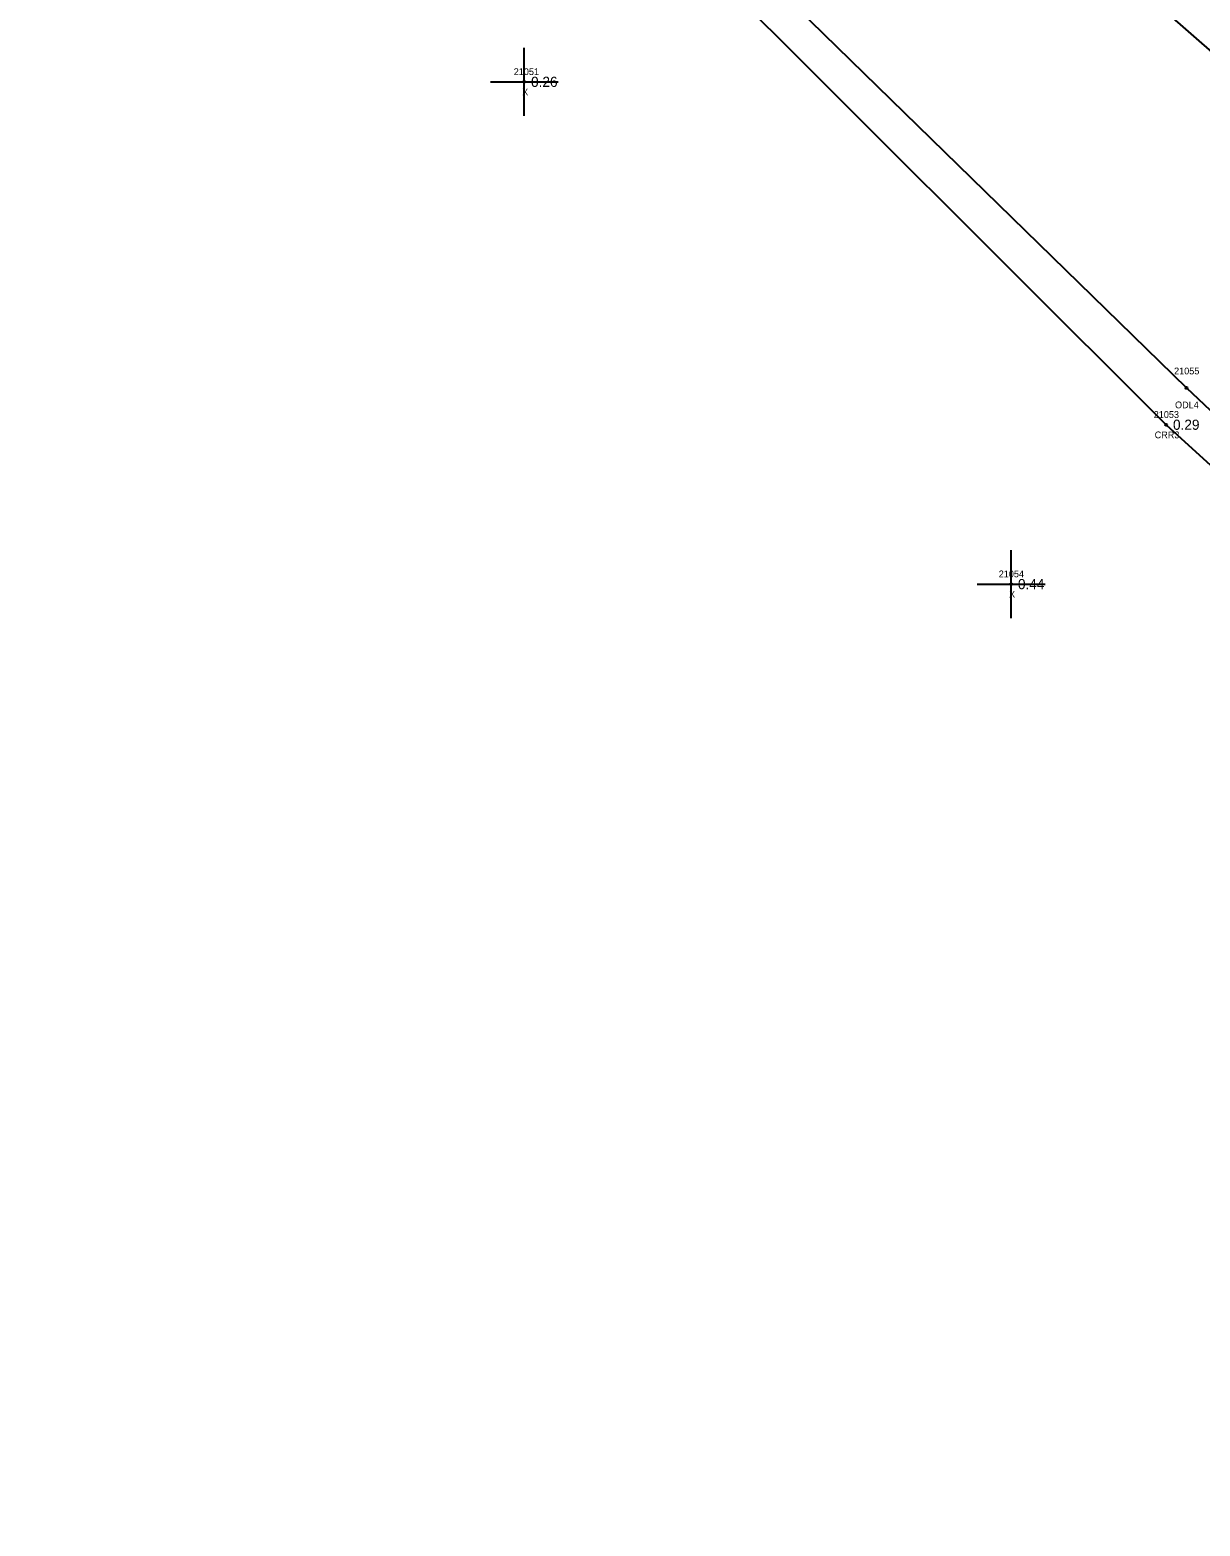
# Model space of a CAD drawing. Extents: x 2608745 to 2610333, y 641917 to 643463.
# Drawn here: x 2609542.9 to 2609715.3, y 642225.6 to 642446.2 of the extents above; entities that cross this region are included whole.
import ezdxf

# ---------------------------------------------------------------- set-up
doc = ezdxf.new("R2010")
doc.units = 0
for name, color, linetype in [('RD_EX_H2O', 7, 'Continuous'), ('RD_EX_H2O_txCode', 7, 'Continuous'), ('RD_EX_Misc', 7, 'Continuous'), ('RD_EX_Misc_txCode', 7, 'Continuous'), ('RD_EX_TX_H2O_ELEV', 7, 'Continuous'), ('RD_EX_TX_Misc_ELEV', 7, 'Continuous'), ('RD_SMD_Locator', 7, 'Continuous')]:
    doc.layers.add(name, color=color, linetype=linetype)

msp = doc.modelspace()

# ---------------------------------------------------------------- linework, layer by layer
at = {"layer": 'RD_EX_H2O'}
for points in [[(2609545.26, 642628.98), (2609557.91, 642602.6), (2609591.74, 642540.6), (2609658.48, 642494.06), (2609739.9, 642422.86), (2609760.07, 642378.85), (2609808.54, 642339.07), (2609896.37, 642269.89), (2609925.48, 642240.69), (2609915.11, 642188.91), (2609891.33, 642158.21), (2609835.84, 642063.03)], [(2609518.22, 642586.65), (2609536.97, 642578.99), (2609575.62, 642520.95), (2609643.94, 642461.12), (2609713.29, 642393.38), (2609797.14, 642314.29), (2609845.08, 642297.38), (2609901.61, 642240.2), (2609849.12, 642177.48), (2609793.89, 642090.6)], [(2609514.45, 642579.97), (2609534.32, 642569.3), (2609569.82, 642513.21), (2609640.11, 642458.03), (2609710.3, 642387.96), (2609794.99, 642310.91), (2609843.78, 642290.31), (2609891.67, 642241.7), (2609844.05, 642181.23), (2609787.66, 642090.39)]]:
    msp.add_lwpolyline(points, dxfattribs=at)
at = {"layer": 'RD_EX_Misc'}
for p, q in [((2609615.7, 642433.5), (2609615.7, 642443.5)), ((2609610.7, 642438.5), (2609620.7, 642438.5)), ((2609687.45, 642359.47), (2609687.45, 642369.47)), ((2609682.45, 642364.47), (2609692.45, 642364.47))]:
    msp.add_line(p, q, dxfattribs=at)
at = {"layer": 'RD_SMD_Locator'}
for centre in [(2609615.7, 642438.5), (2609713.29, 642393.38), (2609710.3, 642387.96), (2609687.45, 642364.47)]:
    msp.add_circle(centre, 0.15, dxfattribs=at)

# ---------------------------------------------------------------- texts
at = {"layer": 'RD_EX_H2O_txCode'}
for s, p in [('21055', (2609711.46, 642395.38)), ('ODL4', (2609711.6, 642390.38)), ('21053', (2609708.46, 642388.96)), ('CRR3', (2609708.6, 642385.96))]:
    msp.add_text(s, height=1, dxfattribs=at).set_placement(p)
at = {"layer": 'RD_EX_Misc_txCode'}
for s, p in [('21051', (2609614.15, 642439.5)), ('X', (2609615.39, 642436.5)), ('21054', (2609685.62, 642365.47)), ('X', (2609687.14, 642362.47))]:
    msp.add_text(s, height=1, dxfattribs=at).set_placement(p)
at = {"layer": 'RD_EX_TX_H2O_ELEV'}
msp.add_text('0.29', height=1.5, dxfattribs=at).set_placement((2609711.3, 642387.21))
at = {"layer": 'RD_EX_TX_Misc_ELEV'}
for s, p in [('0.26', (2609616.7, 642437.75)), ('0.44', (2609688.45, 642363.72))]:
    msp.add_text(s, height=1.5, dxfattribs=at).set_placement(p)

doc.saveas('drawing.dxf')
